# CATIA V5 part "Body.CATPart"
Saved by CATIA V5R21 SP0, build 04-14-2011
Part number: Body
Definition: design
Nomenclature: Body
Source: Unknown
Bounding box of the stored display mesh (mm): x -7.5 to 7.5, y -8.826 to 8, z -0.7 to 0.7
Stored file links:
  C:\Users\beatr\OneDrive\Documents\UNB\2026_1\Pi1\Componentes eletronicos\Encoder\Body.CATPart
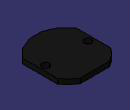
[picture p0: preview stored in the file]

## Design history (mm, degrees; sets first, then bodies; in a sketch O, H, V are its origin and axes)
Body1 "MANIFOLD_SOLID_BREP #69" (main body)
  Solid1: solid without history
